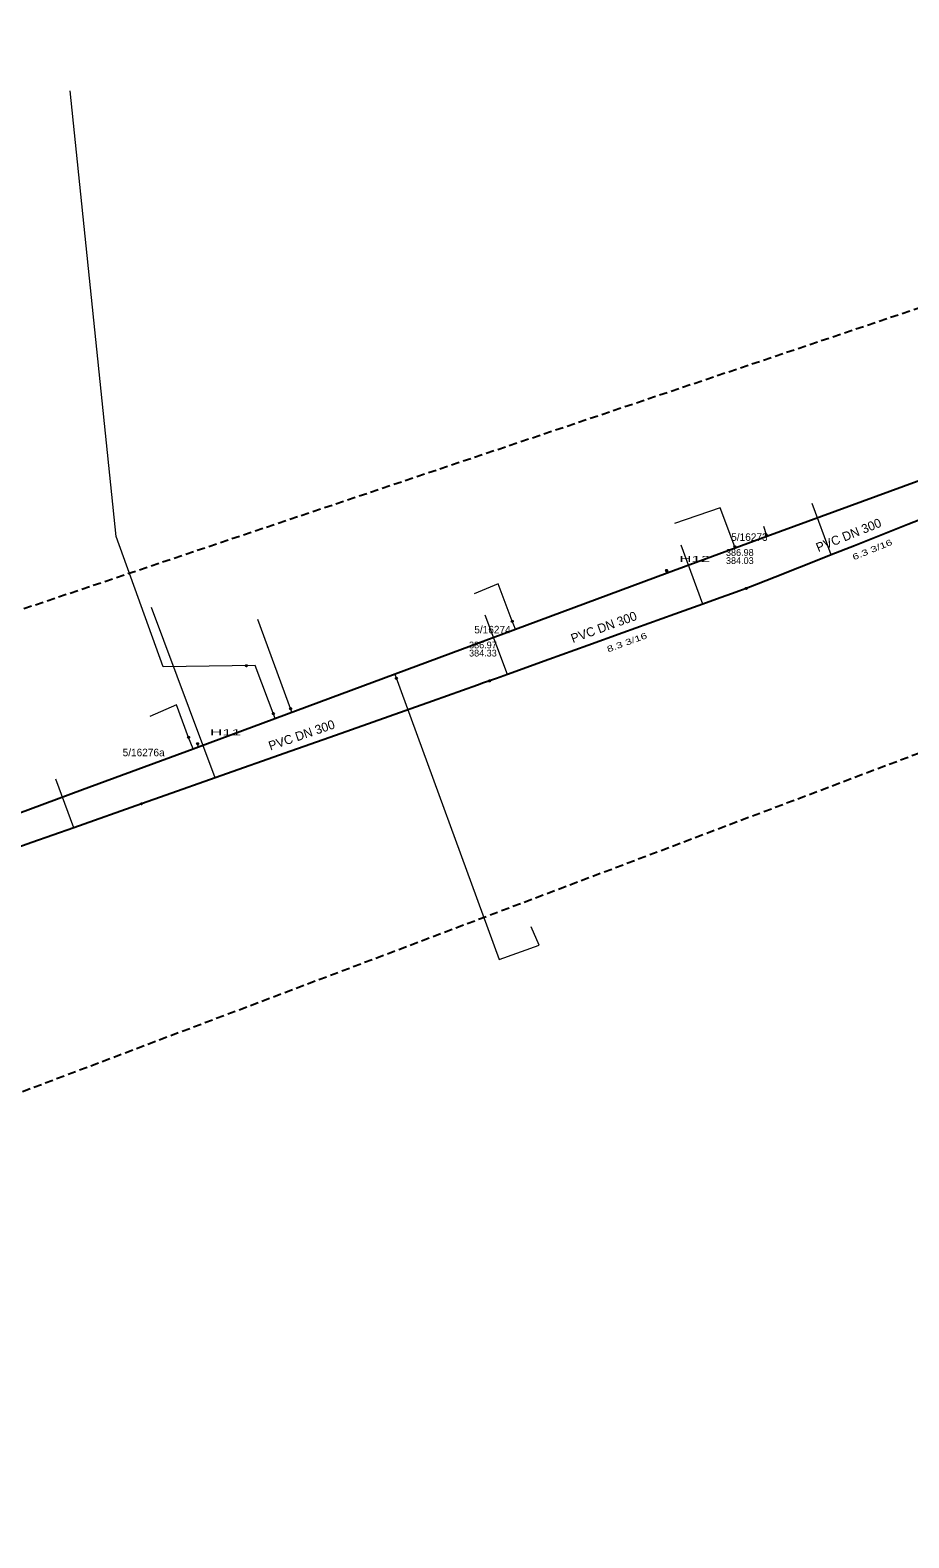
# Model space of a CAD drawing. Extents: x -772855 to -772151, y -1033136 to -1032581.
# Drawn here: x -772598 to -772481.3, y -1033111.6 to -1032911.1 of the extents above; entities that cross this region are included whole.
import ezdxf

# ---------------------------------------------------------------- set-up
doc = ezdxf.new("R2010")
doc.units = 0
doc.header["$LTSCALE"] = 0.36
doc.header["$PDMODE"] = 32
doc.header["$PDSIZE"] = 0.18
doc.linetypes.add('MEDIUM_DASHED', pattern=[4.5, 3, -1.5])
for name, color, linetype in [('15', 7, 'Continuous'), ('20', 7, 'Continuous'), ('21', 7, 'Continuous'), ('3', 7, 'Continuous'), ('4', 7, 'Continuous'), ('5', 7, 'Continuous'), ('56', 7, 'Continuous')]:
    doc.layers.add(name, color=color, linetype=linetype)
for name, color, linetype, lineweight in [('16', 7, 'Continuous', 25), ('2', 7, 'Continuous', 25), ('57', 7, 'Continuous', 13), ('58', 7, 'Continuous', 13), ('62', 7, 'MEDIUM_DASHED', 25)]:
    doc.layers.add(name, color=color, linetype=linetype, lineweight=lineweight)

msp = doc.modelspace()

# ---------------------------------------------------------------- linework, layer by layer
at = {"layer": '15'}
for p in [(-772500.219, -1032978.229), (-772504.41, -1032979.79), (-772513.445, -1032983.079), (-772533.99, -1032989.699), (-772549.382, -1032997.296), (-772563.443, -1033001.309), (-772565.732, -1033001.972), (-772576.99, -1033005.14)]:
    msp.add_point(p, dxfattribs=at)
at = {"layer": '16'}
msp.add_lwpolyline([(-772601.451, -1033015.905), (-772591.094, -1033012.087), (-772576.384, -1033006.664), (-772575.686, -1033006.407), (-772533.557, -1032990.768), (-772513.381, -1032983.278), (-772504.351, -1032979.926), (-772500.166, -1032978.372), (-772474.732, -1032969.061), (-772453.383, -1032960.774), (-772415.739, -1032946.164)], dxfattribs=at)
at = {"layer": '2'}
for points in [[(-772471.89, -1032973.08), (-772472.428, -1032973.292), (-772472.961, -1032973.503), (-772474.98, -1032974.302), (-772477.998, -1032975.495), (-772481.402, -1032976.842), (-772485.412, -1032978.428), (-772488.512, -1032979.653), (-772491.616, -1032980.881), (-772492.384, -1032981.185), (-772495.816, -1032982.542), (-772499.052, -1032983.822), (-772501.537, -1032984.805), (-772502.334, -1032985.12), (-772502.89, -1032985.34)], [(-772502.89, -1032985.34), (-772503.895, -1032985.702), (-772504.742, -1032986.007), (-772506.354, -1032986.588), (-772508.657, -1032987.423), (-772512.392, -1032988.763), (-772519.31, -1032991.256), (-772523.929, -1032992.92), (-772529.122, -1032994.791), (-772534.633, -1032996.776), (-772536.071, -1032997.294), (-772537.03, -1032997.64)], [(-772537.03, -1032997.64), (-772537.789, -1032997.908), (-772538.622, -1032998.202), (-772544.579, -1033000.307), (-772558.238, -1033005.134), (-772563.413, -1033006.963), (-772573.464, -1033010.515), (-772579.964, -1033012.812), (-772583.257, -1033013.976)], [(-772583.257, -1033013.976), (-772592.248, -1033017.153), (-772597.845, -1033019.131), (-772601.075, -1033020.273), (-772610.92, -1033023.751), (-772620.479, -1033027.13), (-772622.362, -1033027.823), (-772626.45, -1033029.24)]]:
    msp.add_lwpolyline(points, dxfattribs=at)
at = {"layer": '20'}
for p in [(-772513.49, -1032982.94), (-772575.804, -1033005.982)]:
    msp.add_point(p, dxfattribs=at)
at = {"layer": '21'}
msp.add_point((-772569.319, -1032995.618), dxfattribs=at)
at = {"layer": '4'}
for p in [(-772502.89, -1032985.34), (-772537.03, -1032997.64), (-772583.257, -1033013.976)]:
    msp.add_point(p, dxfattribs=at)
at = {"layer": '57'}
for p, q in [((-772491.616, -1032980.881), (-772494.14, -1032974.06)), ((-772508.657, -1032987.423), (-772511.56, -1032979.58)), ((-772573.464, -1033010.515), (-772581.91, -1032987.88)), ((-772534.633, -1032996.776), (-772537.6, -1032988.87)), ((-772592.248, -1033017.153), (-772594.64, -1033010.69))]:
    msp.add_line(p, q, dxfattribs=at)
at = {"layer": '58'}
for p, q in [((-772563.264, -1033001.795), (-772567.799, -1032989.468)), ((-772575.684, -1033006.406), (-772575.804, -1033005.982))]:
    msp.add_line(p, q, dxfattribs=at)
for points in [[(-772565.485, -1033002.62), (-772568.154, -1032995.604), (-772580.379, -1032995.749), (-772586.637, -1032978.43), (-772592.75, -1032919.196)], [(-772504.351, -1032979.926), (-772504.41, -1032979.79), (-772506.36, -1032974.6), (-772512.45, -1032976.69)], [(-772500.167, -1032978.373), (-772500.219, -1032978.229), (-772500.561, -1032977.088)], [(-772513.381, -1032983.278), (-772513.445, -1032983.079), (-772513.49, -1032982.94)], [(-772533.557, -1032990.768), (-772533.99, -1032989.7), (-772535.87, -1032984.71), (-772539.03, -1032986.07)], [(-772549.592, -1032996.72), (-772535.744, -1033034.687), (-772530.413, -1033032.783), (-772531.48, -1033030.346)], [(-772576.384, -1033006.664), (-772576.99, -1033005.14), (-772578.61, -1033000.83), (-772582.13, -1033002.35)]]:
    msp.add_lwpolyline(points, dxfattribs=at)
at = {"layer": '62'}
msp.add_lwpolyline([(-772807.858, -1033073.22), (-772807.858, -1033073.204), (-772761.644, -1033042.737), (-772462.077, -1032942.017), (-772241.248, -1032806.814), (-772216.072, -1032836.7), (-772367.717, -1032964.854), (-772756.015, -1033111.568)], close=True, dxfattribs=at)

# ---------------------------------------------------------------- texts
at = {"layer": '20', "width": 2.1}
for s, p in [('H12 ', (-772511.789, -1032981.816)), ('H11 ', (-772574.144, -1033004.858))]:
    msp.add_text(s, height=0.8, dxfattribs=at).set_placement(p)
at = {"layer": '3'}
for rotation, p in [(22, (-772493.327, -1032980.513)), (20, (-772525.934, -1032992.608)), (19, (-772566.124, -1033006.891))]:
    msp.add_text('PVC DN 300', height=1.2, rotation=rotation, dxfattribs=at).set_placement(p)
at = {"layer": '3', "width": 1.45}
for s, rotation, p in [('6.3 3/16 ', 22, (-772488.595, -1032981.596)), ('8.3 3/16 ', 20, (-772521.238, -1032993.837))]:
    msp.add_text(s, height=0.8, rotation=rotation, dxfattribs=at).set_placement(p)
at = {"layer": '5'}
for s, p in [('5/16273', (-772504.89, -1032979.011)), ('5/16274', (-772539.03, -1032991.311)), ('5/16276a ', (-772585.756, -1033007.648))]:
    msp.add_text(s, height=1, dxfattribs=at).set_placement(p)
at = {"layer": '56'}
for s, p in [('386.98', (-772505.588, -1032981.007)), ('384.03', (-772505.588, -1032982.084)), ('386.97', (-772539.728, -1032993.307)), ('384.33', (-772539.728, -1032994.384))]:
    msp.add_text(s, height=0.9, dxfattribs=at).set_placement(p)

doc.saveas('drawing.dxf')
